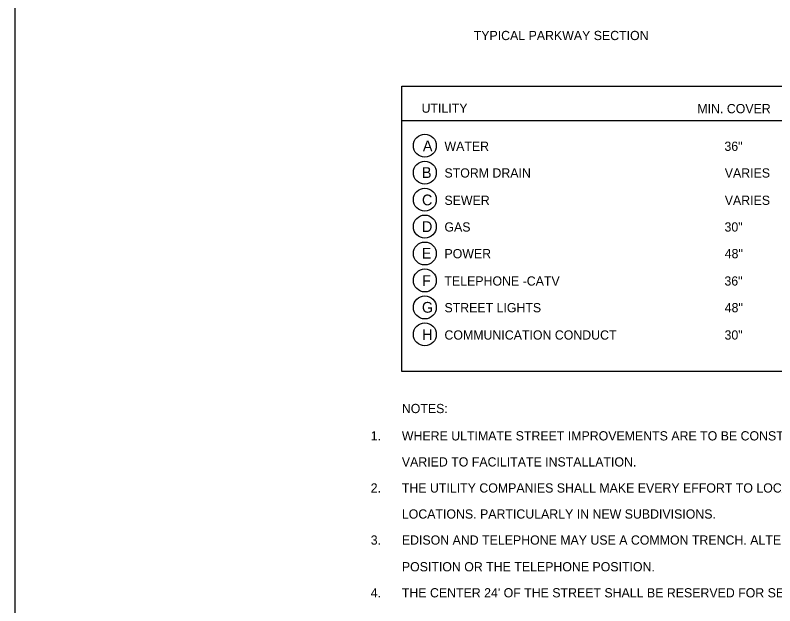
# Model space of a CAD drawing. Extents: x -119017 to -116080, y -104449 to -102845.
# Drawn here: x -119016.8 to -118523, y -103633 to -103248.8 of the extents above; entities that cross this region are included whole.
import ezdxf

# ---------------------------------------------------------------- set-up
doc = ezdxf.new("R2010")
doc.units = 0
doc.layers.add('Default', color=7, linetype='Continuous')
doc.layers.add('Misc CnstDet(22)', color=7, linetype='Continuous')

msp = doc.modelspace()

# ---------------------------------------------------------------- linework, layer by layer
at = {"layer": 'Default'}
msp.add_lwpolyline([(-119016.83, -102845.16), (-117223.08, -102845.16), (-117223.08, -104295.16), (-119016.83, -104295.16)], close=True, dxfattribs=at)
at = {"layer": 'Misc CnstDet(22)'}
msp.add_line((-118765.5, -103317.41), (-118501.34, -103317.41), dxfattribs=at)
msp.add_lwpolyline([(-118765.5, -103295.08), (-118501.34, -103295.08), (-118501.34, -103480.69), (-118765.5, -103480.69)], close=True, dxfattribs=at)
for centre in [(-118750.51, -103333.69), (-118750.51, -103351.23), (-118750.51, -103368.77), (-118750.51, -103386.31), (-118750.51, -103403.84), (-118750.51, -103421.38), (-118750.51, -103438.92), (-118750.51, -103456.46)]:
    msp.add_circle(centre, 7.47, dxfattribs=at)

# ---------------------------------------------------------------- texts
for s, height, p in [('TYPICAL PARKWAY SECTION', 6, (-118718.73, -103265.02)), ('UTILITY', 6, (-118752.63, -103312.27)), ('MIN. COVER', 6, (-118573.34, -103312.59)), ('A', 7, (-118751.79, -103337.35)), ('WATER', 6, (-118737.75, -103337.07)), ('36"', 6, (-118555.73, -103337.07)), ('B', 7, (-118752.39, -103354.71)), ('STORM DRAIN', 6, (-118737.75, -103354.43)), ('VARIES', 6, (-118555.52, -103354.43)), ('C', 7, (-118752.38, -103372.49)), ('SEWER', 6, (-118737.75, -103372.21)), ('VARIES', 6, (-118555.52, -103372.21)), ('D', 7, (-118752.37, -103389.85)), ('GAS', 6, (-118737.75, -103389.57)), ('30"', 6, (-118555.67, -103389.57)), ('E', 7, (-118752.49, -103407.21)), ('POWER', 6, (-118737.75, -103406.93)), ('48"', 6, (-118555.55, -103406.93)), ('F', 7, (-118752.35, -103424.99)), ('TELEPHONE -CATV', 6, (-118737.75, -103424.71)), ('36"', 6, (-118555.73, -103424.71)), ('G', 7, (-118752.41, -103442.35)), ('STREET LIGHTS', 6, (-118737.75, -103442.07)), ('48"', 6, (-118555.55, -103442.07)), ('H', 7, (-118752.28, -103460.12)), ('COMMUNICATION CONDUCT', 6, (-118737.75, -103459.84)), ('30"', 6, (-118555.67, -103459.84)), ('NOTES:', 6, (-118765.45, -103507.67)), ('1.', 6, (-118785.7, -103525.45)), ('WHERE ULTIMATE STREET IMPROVEMENTS ARE TO BE CONSTRUCTED, MINIMUM COVER OF UTILITY LINE MAY BE', 6, (-118765.45, -103525.45)), ('VARIED TO FACILITATE INSTALLATION.', 6, (-118765.45, -103542.4)), ('2.', 6, (-118785.7, -103559.35)), ('THE UTILITY COMPANIES SHALL MAKE EVERY EFFORT TO LOCATE THEIR FACILITIES IN THE RECOMMENDED', 6, (-118765.45, -103559.35)), ('LOCATIONS. PARTICULARLY IN NEW SUBDIVISIONS.', 6, (-118765.45, -103576.29)), ('3.', 6, (-118785.7, -103593.24)), ('EDISON AND TELEPHONE MAY USE A COMMON TRENCH. ALTERNATE LOCATION MAY BE EITHER THE EDISON', 6, (-118765.45, -103593.24)), ('POSITION OR THE TELEPHONE POSITION.', 6, (-118765.45, -103610.61)), ('4.', 6, (-118785.7, -103627.55)), ("THE CENTER 24' OF THE STREET SHALL BE RESERVED FOR SEWER AND STORM DRAIN INSTALLATION.", 6, (-118765.45, -103627.55))]:
    msp.add_text(s, height=height, dxfattribs=at).set_placement(p)

doc.saveas('drawing.dxf')
